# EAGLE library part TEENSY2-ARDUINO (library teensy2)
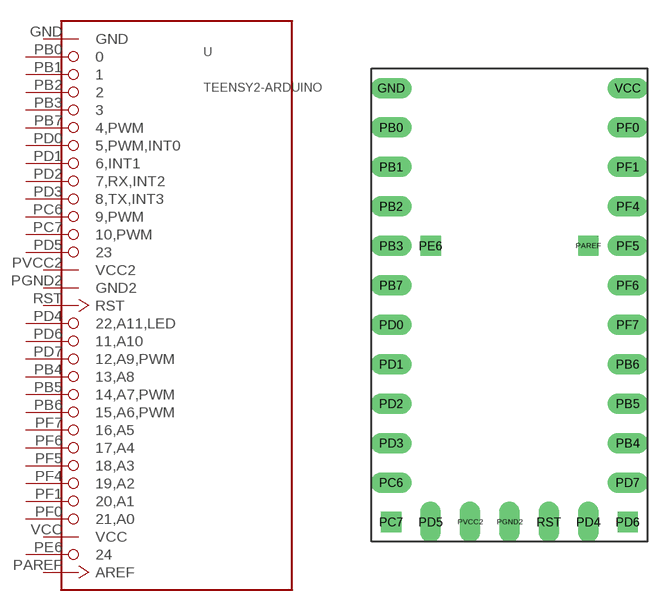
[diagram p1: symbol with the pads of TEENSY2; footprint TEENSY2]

Designator prefix -

## TEENSY2-ARDUINO  [TEENSY2]
GND  GND  pwr
PAREF  AREF  in
PB0  0
PB1  1
PB2  2
PB3  3
PB4  13,A8
PB5  14,A7,PWM
PB6  15,A6,PWM
PB7  4,PWM
PC6  9,PWM
PC7  10,PWM
PD0  5,PWM,INT0
PD1  6,INT1
PD2  7,RX,INT2
PD3  8,TX,INT3
PD4  22,A11,LED
PD5  23
PD6  11,A10
PD7  12,A9,PWM
PE6  24
PF0  21,A0
PF1  20,A1
PF4  19,A2
PF5  18,A3
PF6  17,A4
PF7  16,A5
PGND2  GND2  pwr
PVCC2  VCC2  pwr
RST  RST  in
VCC  VCC  pwr

## Footprint TEENSY2 (pad centres in mm)
http://pjrc.com/teensy/index.html
drill 0.8 long: GND 12.7,21.59; PB0 12.7,19.05; PB1 12.7,16.51; PB2 12.7,13.97; PB3 12.7,11.43; PB4 27.94,-1.27; PB5 27.94,1.27; PB6 27.94,3.81; PB7 12.7,8.89; PC6 12.7,-3.81; PD0 12.7,6.35; PD1 12.7,3.81; PD2 12.7,1.27; PD3 12.7,-1.27; PD4 25.4,-6.35; PD5 15.24,-6.35; PD7 27.94,-3.81; PF0 27.94,19.05; PF1 27.94,16.51; PF4 27.94,13.97; PF5 27.94,11.43; PF6 27.94,8.89; PF7 27.94,6.35; PGND2 20.32,-6.35; PVCC2 17.78,-6.35; RST 22.86,-6.35; VCC 27.94,21.59
drill 0.8 square: PAREF 25.4,11.43; PC7 12.7,-6.35; PD6 27.94,-6.35; PE6 15.24,11.43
